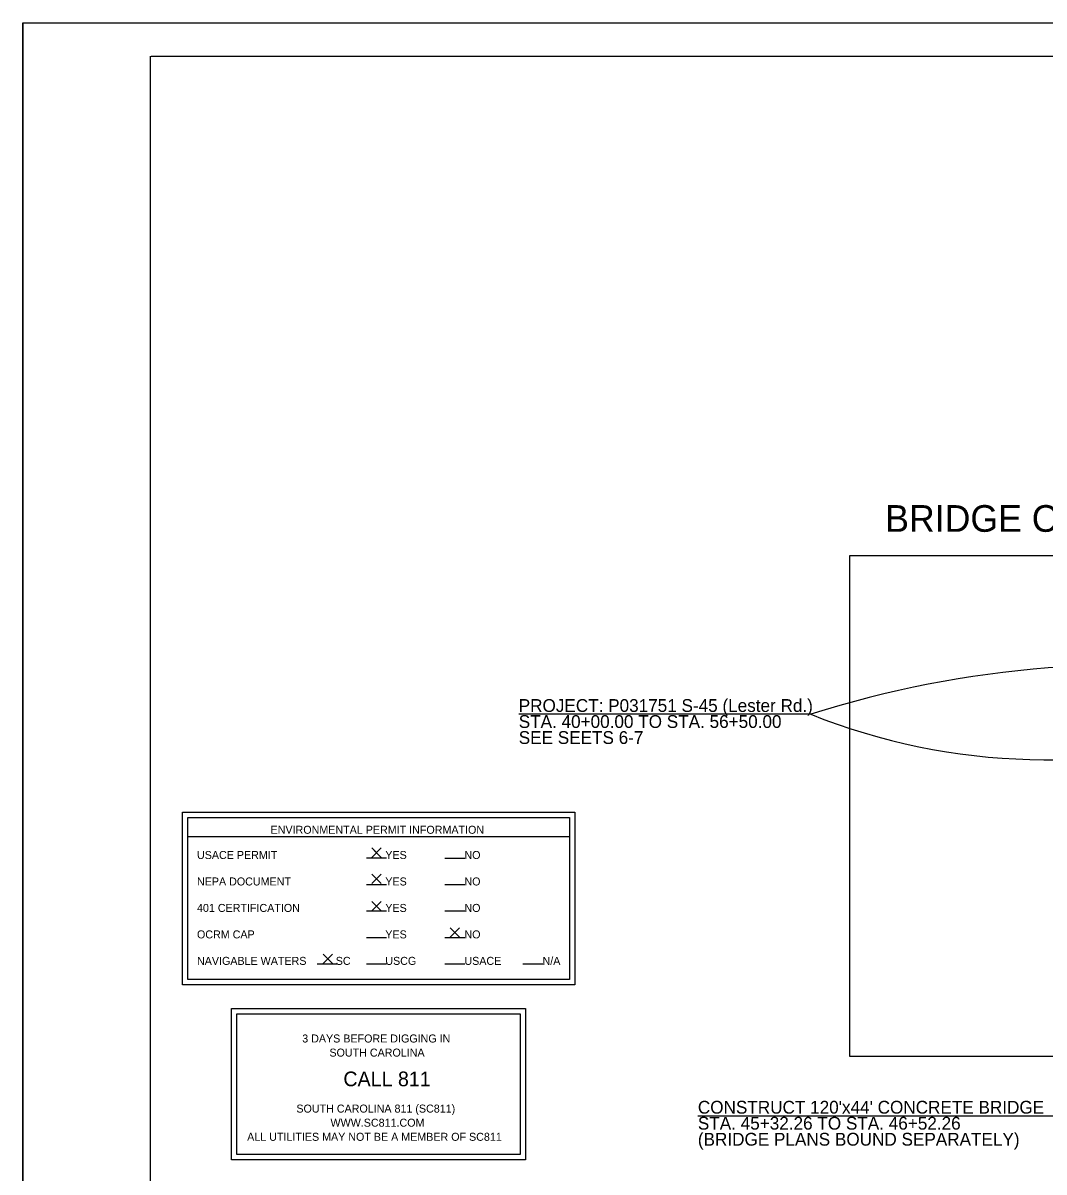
# Model space of a CAD drawing. Extents: x 178032 to 180477, y 178203 to 180757.
# Drawn here: x 178032 to 178798, y 178651 to 179513 of the extents above; entities that cross this region are included whole.
import ezdxf

# ---------------------------------------------------------------- set-up
doc = ezdxf.new("R2010")
doc.units = 0
for name, color, linetype in [('GN_TitleSheetMap', 7, 'Continuous'), ('RD_PD_Final_TX', 7, 'Continuous'), ('RD_SHT_Bndy', 7, 'Continuous'), ('RD_SHT_IplotShp', 7, 'Continuous'), ('RD_SHT_Snap', 7, 'Continuous'), ('RD_SHT_TX', 7, 'Continuous'), ('RD_TX_TitleSht', 7, 'Continuous')]:
    doc.layers.add(name, color=color, linetype=linetype)

msp = doc.modelspace()

# ---------------------------------------------------------------- linework, layer by layer
at = {"layer": 'GN_TitleSheetMap'}
msp.add_lwpolyline([(178651.98, 178738.14), (179276.98, 178738.14), (179276.98, 179113.14), (178651.98, 179113.14)], close=True, dxfattribs=at)
at = {"layer": 'RD_PD_Final_TX'}
for p, q in [((178622.81, 178994.34), (178403.95, 178994.34)), ((178806.34, 178693.22), (178538.22, 178693.22))]:
    msp.add_line(p, q, dxfattribs=at)
for centre, radius, start, end in [((178862.46, 178240.44), 791.07, 81.32066, 107.63394), ((178800.03, 179438.17), 477.91, 248.23368, 288.67139)]:
    msp.add_arc(centre, radius, start, end, dxfattribs=at)
at = {"layer": 'RD_SHT_Bndy'}
for p, q in [((178048.25, 179512.54), (179808.23, 179512.54)), ((178127.88, 178437.54), (178127.88, 179487.59)), ((179803.28, 179487.54), (178128.38, 179487.54))]:
    msp.add_line(p, q, dxfattribs=at)
for points in [[(178188.72, 178773.87), (178409.06, 178773.87), (178409.06, 178660.37), (178188.72, 178660.37)], [(178192.72, 178769.87), (178405.06, 178769.87), (178405.06, 178664.37), (178192.72, 178664.37)]]:
    msp.add_lwpolyline(points, close=True, dxfattribs=at)
at = {"layer": 'RD_SHT_IplotShp'}
msp.add_lwpolyline([(178032.38, 179512.54), (179828.38, 179512.54), (179828.38, 178412.54), (178032.38, 178412.54)], close=True, dxfattribs=at)
at = {"layer": 'RD_SHT_Snap'}
msp.add_line((178032.38, 179512.54), (178032.38, 178412.54), dxfattribs=at)
at = {"layer": 'RD_SHT_TX'}
for p, q in [((178155.85, 178902.79), (178441.97, 178902.79)), ((178304.94, 178886.37), (178289.94, 178886.37)), ((178363.48, 178886.35), (178348.48, 178886.35)), ((178304.94, 178866.52), (178289.94, 178866.52)), ((178363.48, 178866.5), (178348.48, 178866.5)), ((178304.94, 178846.68), (178289.94, 178846.68)), ((178363.48, 178846.66), (178348.48, 178846.66)), ((178304.94, 178826.84), (178289.94, 178826.84)), ((178363.48, 178826.82), (178348.48, 178826.82)), ((178267.79, 178807), (178252.79, 178807)), ((178304.94, 178807), (178289.94, 178807)), ((178363.48, 178806.98), (178348.48, 178806.98)), ((178422.03, 178806.98), (178407.03, 178806.98))]:
    msp.add_line(p, q, dxfattribs=at)
for points in [[(178151.85, 178921.04), (178445.94, 178921.04), (178445.94, 178791.61), (178151.85, 178791.61)], [(178155.85, 178917.04), (178441.94, 178917.04), (178441.94, 178795.61), (178155.85, 178795.61)]]:
    msp.add_lwpolyline(points, close=True, dxfattribs=at)
at = {"layer": 'RD_TX_TitleSht'}
for p, q in [((178293.77, 178894.14), (178297.3, 178890.61)), ((178293.77, 178887.07), (178300.84, 178894.14)), ((178293.77, 178894.14), (178300.84, 178887.07)), ((178293.77, 178874.55), (178297.3, 178871.01)), ((178293.77, 178867.48), (178300.84, 178874.55)), ((178293.77, 178874.55), (178300.84, 178867.48)), ((178293.77, 178854.12), (178297.3, 178850.59)), ((178293.77, 178847.05), (178300.84, 178854.12)), ((178293.77, 178854.12), (178300.84, 178847.05)), ((178352.53, 178834.34), (178356.07, 178830.8)), ((178352.53, 178827.27), (178359.61, 178834.34)), ((178352.53, 178834.34), (178359.61, 178827.27)), ((178257.29, 178807.44), (178264.36, 178814.51)), ((178257.29, 178814.51), (178264.36, 178807.44)), ((178257.29, 178814.51), (178260.83, 178810.98))]:
    msp.add_line(p, q, dxfattribs=at)

# ---------------------------------------------------------------- texts
at = {"layer": 'RD_PD_Final_TX'}
for s, p in [('PROJECT: P031751 S-45 (Lester Rd.)', (178403.95, 178996.1)), ('STA. 40+00.00 TO STA. 56+50.00', (178403.95, 178984.1)), ('SEE SEETS 6-7', (178403.95, 178972.1)), ("CONSTRUCT 120'x44' CONCRETE BRIDGE", (178538.22, 178694.99)), ('STA. 45+32.26 TO STA. 46+52.26', (178538.22, 178682.99)), ('(BRIDGE PLANS BOUND SEPARATELY)', (178538.22, 178670.99))]:
    msp.add_text(s, height=9.6, dxfattribs=at).set_placement(p)
at = {"layer": 'RD_SHT_TX'}
for s, height, p in [('ENVIRONMENTAL PERMIT INFORMATION', 6, (178217.97, 178904.79)), ('USACE PERMIT', 6, (178162.81, 178885.87)), ('YES', 6, (178303.96, 178885.87)), ('NO', 6, (178363.25, 178885.87)), ('NEPA DOCUMENT', 6, (178162.81, 178866.03)), ('YES', 6, (178303.96, 178866.03)), ('NO', 6, (178363.25, 178866.03)), ('401 CERTIFICATION', 6, (178162.81, 178846.19)), ('YES', 6, (178303.96, 178846.19)), ('NO', 6, (178363.25, 178846.19)), ('OCRM CAP', 6, (178162.81, 178826.35)), ('YES', 6, (178303.96, 178826.35)), ('NO', 6, (178363.25, 178826.35)), ('NAVIGABLE WATERS', 6, (178162.81, 178806.5)), ('SC', 6, (178266.8, 178806.5)), ('USCG', 6, (178303.96, 178806.5)), ('USACE', 6, (178363.25, 178806.5)), ('N/A', 6, (178421.79, 178806.5)), ('3 DAYS BEFORE DIGGING IN', 6, (178241.69, 178748.32)), ('SOUTH CAROLINA', 6, (178262.07, 178737.75)), ('CALL 811', 11, (178272.54, 178715.54)), ('SOUTH CAROLINA 811 (SC811)', 6, (178237.3, 178695.78)), ('WWW.SC811.COM', 6, (178262.87, 178685.2)), ('ALL UTILITIES MAY NOT BE A MEMBER OF SC811', 6, (178200.42, 178674.63))]:
    msp.add_text(s, height=height, dxfattribs=at).set_placement(p)
at = {"layer": 'RD_TX_TitleSht'}
msp.add_text('BRIDGE OVER LITTLE PEE DEE SWAMP', height=20, dxfattribs=at).set_placement((178678.59, 179131.13))

doc.saveas('drawing.dxf')
